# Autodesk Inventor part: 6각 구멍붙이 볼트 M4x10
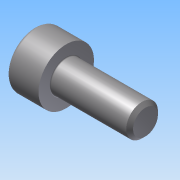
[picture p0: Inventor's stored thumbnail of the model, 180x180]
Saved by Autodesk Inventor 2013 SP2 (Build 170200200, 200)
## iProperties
Created: 2025-10
Part Number: 6각 구멍붙이 볼트 M4x10
Material: Generic
Document SubType Name: Modeling
Designer: 601
Density: 1 g/cm^3
Author: 601
변환 표준: STEP AP214IS
전처리기: Build: 200, Release: 2013 SP2 Update 6 - Date: Thu 07/17/2014
전송 단위: 밀리미터
불확실성: 0.01
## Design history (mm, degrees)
node "6각 구멍붙이 볼트 M4x101"
body "Solid1"
node "기준1"
